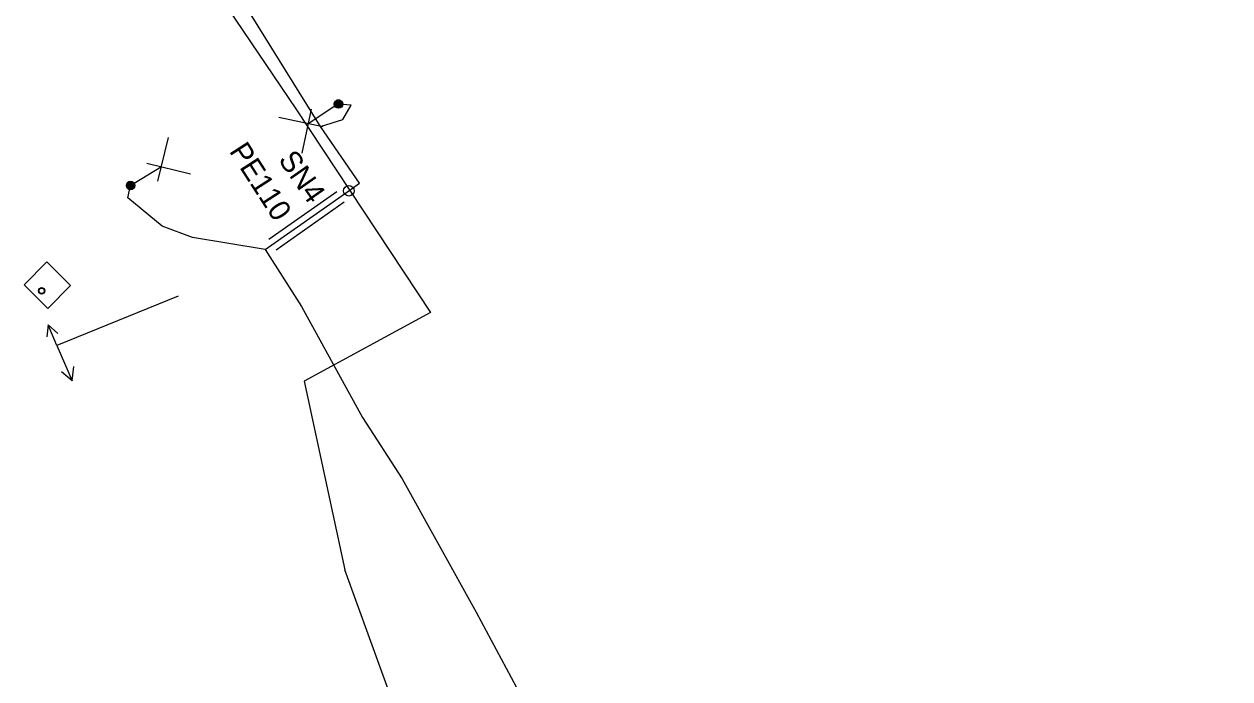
# Model space of a CAD drawing. Extents: x -731967 to -723173, y -945358 to -941505.
# Drawn here: x -725855.1 to -725798.3, y -942371.5 to -942340.7 of the extents above; entities that cross this region are included whole.
import ezdxf

# ---------------------------------------------------------------- set-up
doc = ezdxf.new("R2010")
doc.units = 0
for name, color, linetype in [('Vrstva 2', 7, 'Continuous'), ('Vrstva 28', 7, 'Continuous'), ('Vrstva 35', 7, 'Continuous')]:
    doc.layers.add(name, color=color, linetype=linetype)

msp = doc.modelspace()

# ---------------------------------------------------------------- linework, layer by layer
at = {"layer": 'Vrstva 2'}
for p, q in [((-725841.538, -942344.707), (-725841.976, -942346.783)), ((-725841.538, -942344.707), (-725841.976, -942346.783)), ((-725840.427, -942344.579), (-725841.685, -942345.399)), ((-725840.427, -942344.579), (-725841.685, -942345.399)), ((-725840.993, -942345.544), (-725843.068, -942345.106)), ((-725840.993, -942345.544), (-725843.068, -942345.106)), ((-725848.756, -942348.101), (-725848.257, -942346.038)), ((-725848.756, -942348.101), (-725848.257, -942346.038)), ((-725849.87, -942348.196), (-725848.589, -942347.413)), ((-725849.87, -942348.196), (-725848.589, -942347.413)), ((-725849.275, -942347.248), (-725847.214, -942347.747)), ((-725849.275, -942347.248), (-725847.214, -942347.747))]:
    msp.add_line(p, q, dxfattribs=at)
for points in [[(-725840.151, -942344.638), (-725840.083, -942344.555), (-725840.071, -942344.435), (-725840.126, -942344.334), (-725840.212, -942344.286), (-725840.323, -942344.291), (-725840.417, -942344.361), (-725840.451, -942344.457), (-725840.429, -942344.555), (-725840.349, -942344.635), (-725840.243, -942344.653), (-725840.158, -942344.618), (-725840.096, -942344.534), (-725840.093, -942344.425), (-725840.144, -942344.344), (-725840.227, -942344.303), (-725840.331, -942344.315), (-725840.407, -942344.381), (-725840.431, -942344.464), (-725840.406, -942344.557), (-725840.329, -942344.622), (-725840.239, -942344.633), (-725840.163, -942344.597), (-725840.111, -942344.515), (-725840.115, -942344.421), (-725840.16, -942344.357), (-725840.241, -942344.321), (-725840.334, -942344.338), (-725840.392, -942344.397), (-725840.412, -942344.473), (-725840.382, -942344.556), (-725840.313, -942344.608), (-725840.239, -942344.613), (-725840.167, -942344.576), (-725840.127, -942344.499), (-725840.134, -942344.423), (-725840.178, -942344.367), (-725840.256, -942344.339), (-725840.332, -942344.359), (-725840.377, -942344.409), (-725840.391, -942344.481), (-725840.361, -942344.554), (-725840.301, -942344.59), (-725840.237, -942344.591), (-725840.174, -942344.554), (-725840.145, -942344.488), (-725840.154, -942344.428), (-725840.197, -942344.377), (-725840.266, -942344.358), (-725840.326, -942344.379), (-725840.363, -942344.423), (-725840.371, -942344.489), (-725840.341, -942344.545), (-725840.293, -942344.573), (-725840.234, -942344.571), (-725840.183, -942344.535), (-725840.164, -942344.481), (-725840.173, -942344.431), (-725840.215, -942344.389), (-725840.271, -942344.378), (-725840.316, -942344.396), (-725840.347, -942344.437), (-725840.35, -942344.493), (-725840.324, -942344.535), (-725840.284, -942344.555), (-725840.234, -942344.55), (-725840.195, -942344.518), (-725840.184, -942344.477), (-725840.194, -942344.434), (-725840.23, -942344.403), (-725840.273, -942344.398), (-725840.306, -942344.414), (-725840.331, -942344.45), (-725840.329, -942344.492), (-725840.309, -942344.521), (-725840.275, -942344.537), (-725840.236, -942344.53), (-725840.211, -942344.504), (-725840.203, -942344.473), (-725840.215, -942344.44), (-725840.243, -942344.419), (-725840.272, -942344.418), (-725840.298, -942344.432), (-725840.313, -942344.46), (-725840.31, -942344.489), (-725840.294, -942344.509), (-725840.268, -942344.518), (-725840.241, -942344.51), (-725840.226, -942344.493), (-725840.223, -942344.471), (-725840.232, -942344.448), (-725840.251, -942344.436), (-725840.27, -942344.436), (-725840.287, -942344.448), (-725840.295, -942344.466), (-725840.29, -942344.483), (-725840.28, -942344.495), (-725840.264, -942344.499), (-725840.25, -942344.493), (-725840.243, -942344.483), (-725840.242, -942344.469)], [(-725840.151, -942344.638), (-725840.083, -942344.555), (-725840.071, -942344.435), (-725840.126, -942344.334), (-725840.212, -942344.286), (-725840.323, -942344.291), (-725840.417, -942344.361), (-725840.451, -942344.457), (-725840.429, -942344.555), (-725840.349, -942344.635), (-725840.243, -942344.653), (-725840.158, -942344.618), (-725840.096, -942344.534), (-725840.093, -942344.425), (-725840.144, -942344.344), (-725840.227, -942344.303), (-725840.331, -942344.315), (-725840.407, -942344.381), (-725840.431, -942344.464), (-725840.406, -942344.557), (-725840.329, -942344.622), (-725840.239, -942344.633), (-725840.163, -942344.597), (-725840.111, -942344.515), (-725840.115, -942344.421), (-725840.16, -942344.357), (-725840.241, -942344.321), (-725840.334, -942344.338), (-725840.392, -942344.397), (-725840.412, -942344.473), (-725840.382, -942344.556), (-725840.313, -942344.608), (-725840.239, -942344.613), (-725840.167, -942344.576), (-725840.127, -942344.499), (-725840.134, -942344.423), (-725840.178, -942344.367), (-725840.256, -942344.339), (-725840.332, -942344.359), (-725840.377, -942344.409), (-725840.391, -942344.481), (-725840.361, -942344.554), (-725840.301, -942344.59), (-725840.237, -942344.591), (-725840.174, -942344.554), (-725840.145, -942344.488), (-725840.154, -942344.428), (-725840.197, -942344.377), (-725840.266, -942344.358), (-725840.326, -942344.379), (-725840.363, -942344.423), (-725840.371, -942344.489), (-725840.341, -942344.545), (-725840.293, -942344.573), (-725840.234, -942344.571), (-725840.183, -942344.535), (-725840.164, -942344.481), (-725840.173, -942344.431), (-725840.215, -942344.389), (-725840.271, -942344.378), (-725840.316, -942344.396), (-725840.347, -942344.437), (-725840.35, -942344.493), (-725840.324, -942344.535), (-725840.284, -942344.555), (-725840.234, -942344.55), (-725840.195, -942344.518), (-725840.184, -942344.477), (-725840.194, -942344.434), (-725840.23, -942344.403), (-725840.273, -942344.398), (-725840.306, -942344.414), (-725840.331, -942344.45), (-725840.329, -942344.492), (-725840.309, -942344.521), (-725840.275, -942344.537), (-725840.236, -942344.53), (-725840.211, -942344.504), (-725840.203, -942344.473), (-725840.215, -942344.44), (-725840.243, -942344.419), (-725840.272, -942344.418), (-725840.298, -942344.432), (-725840.313, -942344.46), (-725840.31, -942344.489), (-725840.294, -942344.509), (-725840.268, -942344.518), (-725840.241, -942344.51), (-725840.226, -942344.493), (-725840.223, -942344.471), (-725840.232, -942344.448), (-725840.251, -942344.436), (-725840.27, -942344.436), (-725840.287, -942344.448), (-725840.295, -942344.466), (-725840.29, -942344.483), (-725840.28, -942344.495), (-725840.264, -942344.499), (-725840.25, -942344.493), (-725840.243, -942344.483), (-725840.242, -942344.469)], [(-725840.242, -942344.469), (-725840.248, -942344.46), (-725840.258, -942344.456), (-725840.268, -942344.457), (-725840.274, -942344.462), (-725840.276, -942344.47), (-725840.273, -942344.477), (-725840.268, -942344.479), (-725840.263, -942344.48), (-725840.26, -942344.476)], [(-725840.242, -942344.469), (-725840.248, -942344.46), (-725840.258, -942344.456), (-725840.268, -942344.457), (-725840.274, -942344.462), (-725840.276, -942344.47), (-725840.273, -942344.477), (-725840.268, -942344.479), (-725840.263, -942344.48), (-725840.26, -942344.476)], [(-725850.144, -942348.129), (-725850.214, -942348.21), (-725850.23, -942348.329), (-725850.178, -942348.432), (-725850.094, -942348.482), (-725849.982, -942348.481), (-725849.887, -942348.413), (-725849.85, -942348.318), (-725849.868, -942348.22), (-725849.946, -942348.138), (-725850.052, -942348.117), (-725850.138, -942348.149), (-725850.202, -942348.231), (-725850.208, -942348.34), (-725850.16, -942348.423), (-725850.078, -942348.466), (-725849.974, -942348.457), (-725849.896, -942348.393), (-725849.869, -942348.312), (-725849.892, -942348.217), (-725849.967, -942348.15), (-725850.056, -942348.137), (-725850.134, -942348.17), (-725850.188, -942348.251), (-725850.187, -942348.344), (-725850.143, -942348.41), (-725850.063, -942348.449), (-725849.97, -942348.434), (-725849.91, -942348.377), (-725849.888, -942348.302), (-725849.915, -942348.217), (-725849.983, -942348.164), (-725850.057, -942348.157), (-725850.129, -942348.192), (-725850.172, -942348.267), (-725850.167, -942348.344), (-725850.125, -942348.401), (-725850.048, -942348.431), (-725849.971, -942348.413), (-725849.925, -942348.364), (-725849.908, -942348.293), (-725849.937, -942348.219), (-725849.996, -942348.181), (-725850.059, -942348.178), (-725850.123, -942348.214), (-725850.154, -942348.278), (-725850.147, -942348.339), (-725850.106, -942348.392), (-725850.038, -942348.412), (-725849.977, -942348.393), (-725849.939, -942348.35), (-725849.929, -942348.285), (-725849.957, -942348.227), (-725850.004, -942348.198), (-725850.063, -942348.198), (-725850.115, -942348.233), (-725850.136, -942348.286), (-725850.128, -942348.336), (-725850.088, -942348.38), (-725850.032, -942348.392), (-725849.986, -942348.376), (-725849.954, -942348.335), (-725849.949, -942348.28), (-725849.974, -942348.237), (-725850.013, -942348.216), (-725850.064, -942348.22), (-725850.103, -942348.251), (-725850.116, -942348.291), (-725850.107, -942348.334), (-725850.072, -942348.366), (-725850.029, -942348.373), (-725849.995, -942348.358), (-725849.969, -942348.322), (-725849.97, -942348.28), (-725849.989, -942348.251), (-725850.023, -942348.234), (-725850.062, -942348.239), (-725850.088, -942348.264), (-725850.097, -942348.295), (-725850.086, -942348.329), (-725850.059, -942348.351), (-725850.03, -942348.352), (-725850.003, -942348.339), (-725849.987, -942348.312), (-725849.99, -942348.283), (-725850.005, -942348.262), (-725850.031, -942348.252), (-725850.058, -942348.259), (-725850.073, -942348.276), (-725850.077, -942348.298), (-725850.068, -942348.321), (-725850.05, -942348.334), (-725850.031, -942348.334), (-725850.014, -942348.323), (-725850.006, -942348.305), (-725850.01, -942348.288), (-725850.019, -942348.276), (-725850.035, -942348.271), (-725850.049, -942348.277), (-725850.057, -942348.287), (-725850.058, -942348.3)], [(-725850.144, -942348.129), (-725850.214, -942348.21), (-725850.23, -942348.329), (-725850.178, -942348.432), (-725850.094, -942348.482), (-725849.982, -942348.481), (-725849.887, -942348.413), (-725849.85, -942348.318), (-725849.868, -942348.22), (-725849.946, -942348.138), (-725850.052, -942348.117), (-725850.138, -942348.149), (-725850.202, -942348.231), (-725850.208, -942348.34), (-725850.16, -942348.423), (-725850.078, -942348.466), (-725849.974, -942348.457), (-725849.896, -942348.393), (-725849.869, -942348.312), (-725849.892, -942348.217), (-725849.967, -942348.15), (-725850.056, -942348.137), (-725850.134, -942348.17), (-725850.188, -942348.251), (-725850.187, -942348.344), (-725850.143, -942348.41), (-725850.063, -942348.449), (-725849.97, -942348.434), (-725849.91, -942348.377), (-725849.888, -942348.302), (-725849.915, -942348.217), (-725849.983, -942348.164), (-725850.057, -942348.157), (-725850.129, -942348.192), (-725850.172, -942348.267), (-725850.167, -942348.344), (-725850.125, -942348.401), (-725850.048, -942348.431), (-725849.971, -942348.413), (-725849.925, -942348.364), (-725849.908, -942348.293), (-725849.937, -942348.219), (-725849.996, -942348.181), (-725850.059, -942348.178), (-725850.123, -942348.214), (-725850.154, -942348.278), (-725850.147, -942348.339), (-725850.106, -942348.392), (-725850.038, -942348.412), (-725849.977, -942348.393), (-725849.939, -942348.35), (-725849.929, -942348.285), (-725849.957, -942348.227), (-725850.004, -942348.198), (-725850.063, -942348.198), (-725850.115, -942348.233), (-725850.136, -942348.286), (-725850.128, -942348.336), (-725850.088, -942348.38), (-725850.032, -942348.392), (-725849.986, -942348.376), (-725849.954, -942348.335), (-725849.949, -942348.28), (-725849.974, -942348.237), (-725850.013, -942348.216), (-725850.064, -942348.22), (-725850.103, -942348.251), (-725850.116, -942348.291), (-725850.107, -942348.334), (-725850.072, -942348.366), (-725850.029, -942348.373), (-725849.995, -942348.358), (-725849.969, -942348.322), (-725849.97, -942348.28), (-725849.989, -942348.251), (-725850.023, -942348.234), (-725850.062, -942348.239), (-725850.088, -942348.264), (-725850.097, -942348.295), (-725850.086, -942348.329), (-725850.059, -942348.351), (-725850.03, -942348.352), (-725850.003, -942348.339), (-725849.987, -942348.312), (-725849.99, -942348.283), (-725850.005, -942348.262), (-725850.031, -942348.252), (-725850.058, -942348.259), (-725850.073, -942348.276), (-725850.077, -942348.298), (-725850.068, -942348.321), (-725850.05, -942348.334), (-725850.031, -942348.334), (-725850.014, -942348.323), (-725850.006, -942348.305), (-725850.01, -942348.288), (-725850.019, -942348.276), (-725850.035, -942348.271), (-725850.049, -942348.277), (-725850.057, -942348.287), (-725850.058, -942348.3)], [(-725850.058, -942348.3), (-725850.052, -942348.31), (-725850.043, -942348.314), (-725850.033, -942348.313), (-725850.026, -942348.308), (-725850.024, -942348.3), (-725850.027, -942348.294), (-725850.032, -942348.291), (-725850.037, -942348.291), (-725850.04, -942348.294)], [(-725850.058, -942348.3), (-725850.052, -942348.31), (-725850.043, -942348.314), (-725850.033, -942348.313), (-725850.026, -942348.308), (-725850.024, -942348.3), (-725850.027, -942348.294), (-725850.032, -942348.291), (-725850.037, -942348.291), (-725850.04, -942348.294)], [(-725843.542, -942350.832), (-725840.33, -942348.577)], [(-725843.542, -942350.832), (-725840.33, -942348.577)], [(-725843.197, -942351.323), (-725839.985, -942349.068)], [(-725843.197, -942351.323), (-725839.985, -942349.068)]]:
    msp.add_lwpolyline(points, dxfattribs=at)
msp.add_lwpolyline([(-725855.051, -942352.97), (-725853.979, -942351.896), (-725852.864, -942353.008), (-725853.936, -942354.082)], close=True, dxfattribs=at)
msp.add_lwpolyline([(-725855.051, -942352.97), (-725853.979, -942351.896), (-725852.864, -942353.008), (-725853.936, -942354.082)], close=True, dxfattribs=at)
for centre, radius in [((-725840.26, -942344.47), 0.2), ((-725840.26, -942344.47), 0.2), ((-725850.04, -942348.3), 0.2), ((-725850.04, -942348.3), 0.2), ((-725839.77, -942348.55), 0.25), ((-725839.77, -942348.55), 0.25), ((-725854.226, -942353.257), 0.15), ((-725854.226, -942353.257), 0.15), ((-725854.226, -942353.257), 0.15), ((-725854.226, -942353.257), 0.15), ((-725854.226, -942353.257), 0.125), ((-725854.226, -942353.257), 0.125)]:
    msp.add_circle(centre, radius, dxfattribs=at)
at = {"layer": 'Vrstva 28'}
for points in [[(-725841.11, -942345.53), (-725848.9, -942332.97), (-725847.06, -942333.17), (-725845.53, -942333.2)], [(-725841.11, -942345.53), (-725848.9, -942332.97), (-725847.06, -942333.17), (-725845.53, -942333.2)], [(-725843.7, -942351.31), (-725839.77, -942348.55), (-725839.27, -942348.2), (-725841.11, -942345.53), (-725840.05, -942345.2), (-725839.66, -942344.52), (-725840.26, -942344.47)], [(-725843.7, -942351.31), (-725839.77, -942348.55), (-725839.27, -942348.2), (-725841.11, -942345.53), (-725840.05, -942345.2), (-725839.66, -942344.52), (-725840.26, -942344.47)], [(-725843.7, -942351.31), (-725847.13, -942350.74), (-725848.55, -942350.21), (-725850.17, -942348.89), (-725850.04, -942348.3)], [(-725843.7, -942351.31), (-725847.13, -942350.74), (-725848.55, -942350.21), (-725850.17, -942348.89), (-725850.04, -942348.3)], [(-725843.7, -942351.31), (-725842, -942354), (-725839.13, -942359.21), (-725837.26, -942362.1), (-725833.78, -942368.36), (-725831.42, -942372.76), (-725829.46, -942376.68), (-725826.7, -942382.34), (-725824.65, -942386.3), (-725818.36, -942402.14), (-725815.26, -942410.73), (-725814.18, -942414.28), (-725811.95, -942421.01), (-725811.25, -942423.82), (-725808.92, -942431.23), (-725808.24, -942433.75), (-725807.25, -942436.52), (-725805.06, -942443.84), (-725804.36, -942448.24), (-725802.42, -942455.17), (-725801.53, -942457.81), (-725799.8, -942466.03), (-725798.31, -942472.16)], [(-725843.7, -942351.31), (-725842, -942354), (-725839.13, -942359.21), (-725837.26, -942362.1), (-725833.78, -942368.36), (-725831.42, -942372.76), (-725829.46, -942376.68), (-725826.7, -942382.34), (-725824.65, -942386.3), (-725818.36, -942402.14), (-725815.26, -942410.73), (-725814.18, -942414.28), (-725811.95, -942421.01), (-725811.25, -942423.82), (-725808.92, -942431.23), (-725808.24, -942433.75), (-725807.25, -942436.52), (-725805.06, -942443.84), (-725804.36, -942448.24), (-725802.42, -942455.17), (-725801.53, -942457.81), (-725799.8, -942466.03), (-725798.31, -942472.16)], [(-725855.051, -942352.97), (-725853.979, -942351.896), (-725852.864, -942353.008), (-725853.936, -942354.082), (-725855.051, -942352.97)], [(-725855.051, -942352.97), (-725853.979, -942351.896), (-725852.864, -942353.008), (-725853.936, -942354.082), (-725855.051, -942352.97)], [(-725847.805, -942353.503), (-725853.512, -942355.826), (-725853.926, -942354.852)], [(-725853.926, -942354.852), (-725853.988, -942355.419)], [(-725853.926, -942354.852), (-725853.468, -942355.261)], [(-725853.512, -942355.826), (-725852.793, -942357.49)], [(-725853.512, -942355.826), (-725852.793, -942357.49)], [(-725852.793, -942357.49), (-725853.296, -942357.064)], [(-725852.793, -942357.49), (-725852.704, -942356.818)]]:
    msp.add_lwpolyline(points, dxfattribs=at)
msp.add_lwpolyline([(-725855.051, -942352.97), (-725853.979, -942351.896), (-725852.864, -942353.008), (-725853.936, -942354.082)], close=True, dxfattribs=at)
msp.add_lwpolyline([(-725855.051, -942352.97), (-725853.979, -942351.896), (-725852.864, -942353.008), (-725853.936, -942354.082)], close=True, dxfattribs=at)
at = {"layer": 'Vrstva 35'}
for p, q in [((-725848.655, -942335.231), (-725842.27, -942344.701)), ((-725842.27, -942344.701), (-725835.929, -942354.276)), ((-725835.929, -942354.276), (-725841.872, -942357.509)), ((-725841.872, -942357.509), (-725839.963, -942366.381)), ((-725829.77, -942394.31), (-725839.963, -942366.381))]:
    msp.add_line(p, q, dxfattribs=at)

# ---------------------------------------------------------------- texts
at = {"layer": 'Vrstva 2'}
for s, rotation, p in [('PE110', 302.8379, (-725845.425, -942346.688)), ('SN4', 304.9477, (-725843.12, -942347.096))]:
    msp.add_text(s, height=1, rotation=rotation, dxfattribs=at).set_placement(p)

doc.saveas('drawing.dxf')
